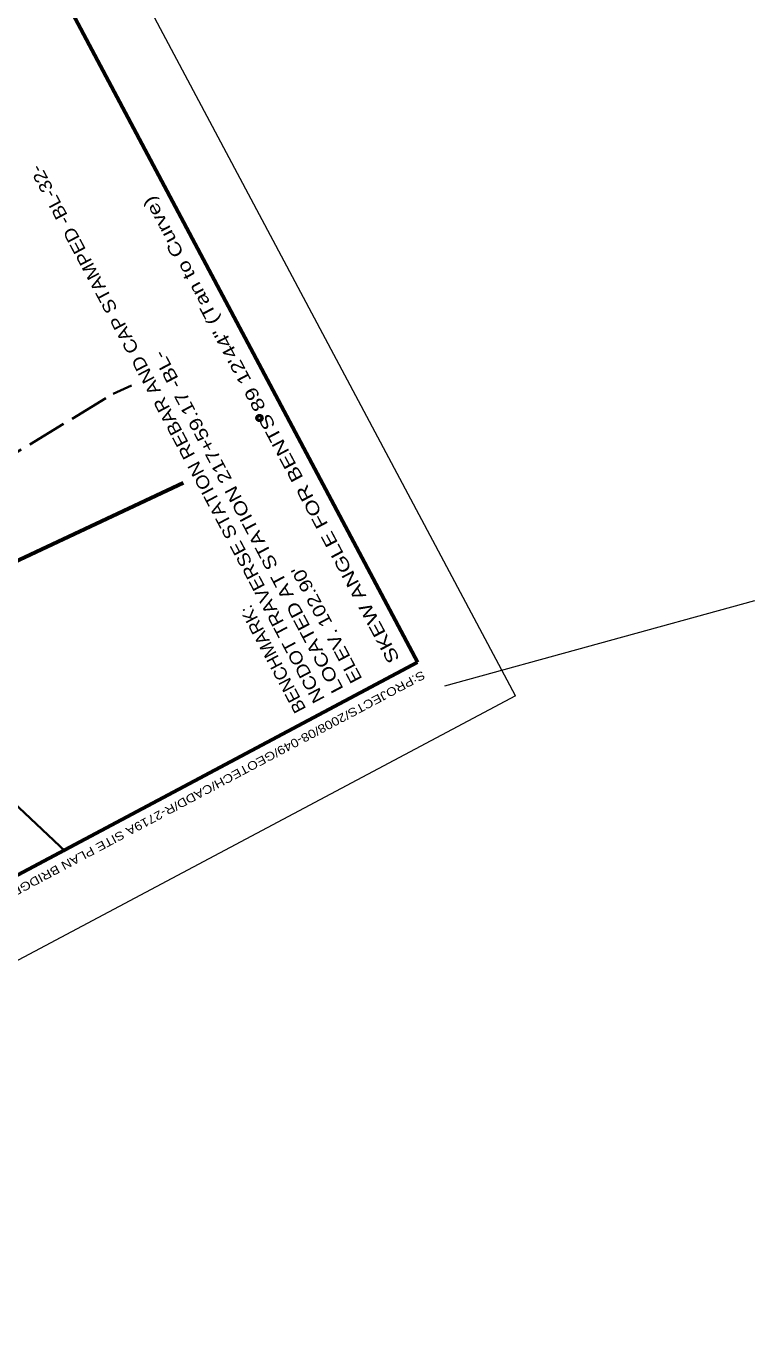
# Model space of a CAD drawing. Extents: x 2402199 to 2404507, y 568050 to 571478.
# Drawn here: x 2402674.4 to 2402829, y 570719 to 570997.1 of the extents above; entities that cross this region are included whole.
import ezdxf

# ---------------------------------------------------------------- set-up
doc = ezdxf.new("R2010")
doc.units = 0
doc.header["$LTSCALE"] = 1.4
doc.linetypes.add('LONG_DASHED', pattern=[7.5, 6, -1.5])
doc.linetypes.add('MEDIUM_DASHED', pattern=[4.5, 3, -1.5])
for name, color, linetype, lineweight in [('17', 7, 'MEDIUM_DASHED', 35), ('6', 7, 'Continuous', 35), ('63', 7, 'Continuous', 35)]:
    doc.layers.add(name, color=color, linetype=linetype, lineweight=lineweight)

msp = doc.modelspace()

# ---------------------------------------------------------------- linework, layer by layer
at = {"layer": '17', "linetype": 'LONG_DASHED'}
for p, q in [((2402692.803, 570919.098), (2402696.726, 570920.864)), ((2402639.183, 570886.623), (2402692.803, 570919.098))]:
    msp.add_line(p, q, dxfattribs=at)
at = {"layer": '17', "linetype": 'Continuous', "lineweight": 60}
msp.add_line((2402707.695, 570900.235), (2402626.394, 570862.088), dxfattribs=at)
at = {"layer": '6'}
msp.add_line((2402682.659, 570821.993), (2402635.453, 570866.339), dxfattribs=at)
at = {"layer": '63', "lineweight": 13}
for p, q in [((2402778.178, 570855.005), (2402538.748, 571305.309)), ((2402763.17, 570857.142), (2402828.95, 570875.226)), ((2402778.178, 570855.005), (2402486.806, 570700.08))]:
    msp.add_line(p, q, dxfattribs=at)
at = {"layer": '63', "lineweight": 60}
for p in [(2402531.138, 571287.671), (2402492.519, 570721.286)]:
    msp.add_line(p, (2402757.403, 570862.128), dxfattribs=at)
at = {"layer": '63', "lineweight": 53}
msp.add_circle((2402723.853, 570913.981), 0.551, dxfattribs=at)

# ---------------------------------------------------------------- texts
at = {"layer": '63'}
for s, height, rotation, width, p in [('NCDOT TRAVERSE STATION REBAR AND CAP STAMPED -BL-32-', 2.7, 118, 1.15, (2402737.792, 570854.375)), ('SKEW ANGLE FOR BENTS 89 12\'44" (Tan to Curve)', 2.7, 118, 1.3, (2402753.685, 570862.825)), ('LOCATED AT STATION 217+59.17 -BL-', 2.7, 118, 1.25, (2402741.765, 570856.488)), ("ELEV. 102.90'", 2.7, 118, 1.2, (2402745.739, 570858.6)), ('BENCHMARK: ', 2.7, 118, 1.05, (2402733.819, 570852.262)), ('S:PROJECTS/2008/08-049/GEOTECH/CADD/R-2719A SITE PLAN BRIDGE 199 RL.DGN', 1.8, 208, 1.2, (2402758.374, 570860.406))]:
    msp.add_text(s, height=height, rotation=rotation, dxfattribs=dict(at, width=width)).set_placement(p)

doc.saveas('drawing.dxf')
